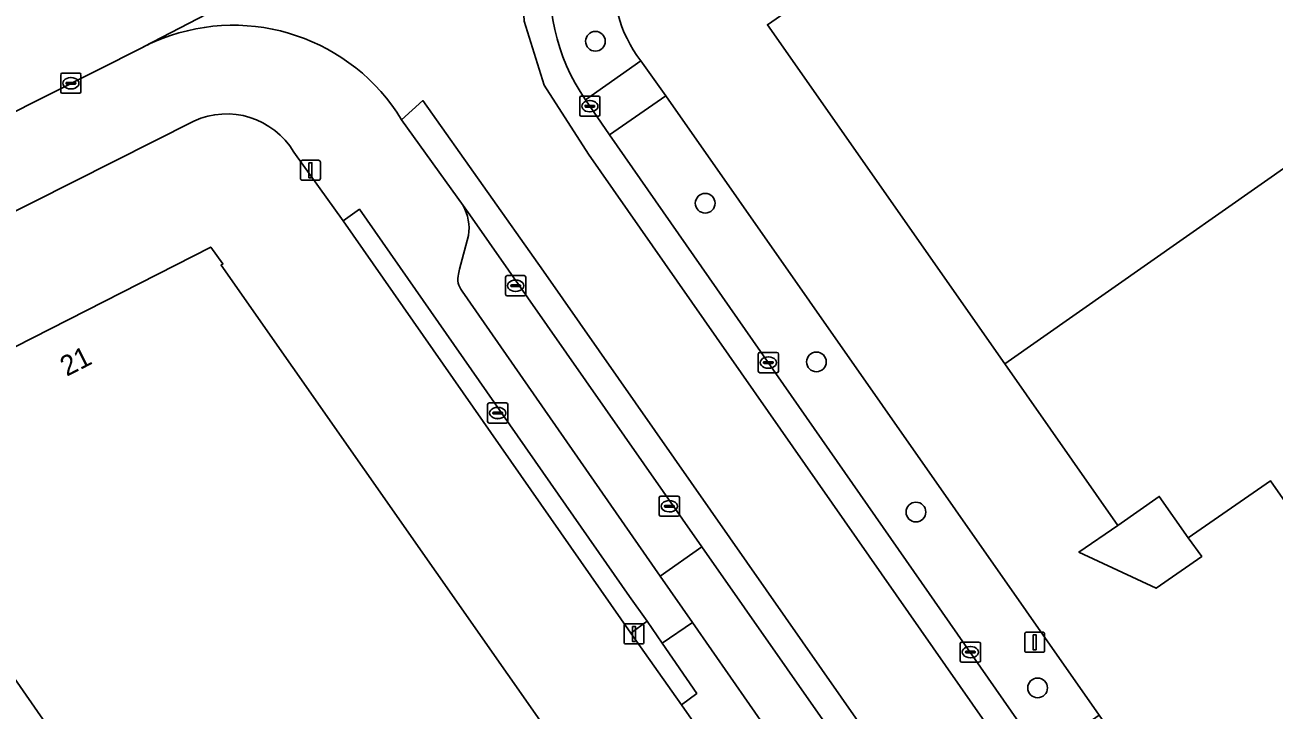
# Model space of a CAD drawing. Extents: x 156702 to 158052, y 387630 to 388992.
# Drawn here: x 157140.6 to 157202.6, y 388268.5 to 388302.5 of the extents above; entities that cross this region are included whole.
import ezdxf

# ---------------------------------------------------------------- set-up
doc = ezdxf.new("R2010")
doc.units = 0
for name, color, linetype in [('IMGEO_Berm_groen', 7, 'Continuous'), ('IMGEO_Boom', 7, 'Continuous'), ('IMGEO_Brandkraan', 7, 'Continuous'), ('IMGEO_Erf', 7, 'Continuous'), ('IMGEO_Groenvoorziening', 7, 'Continuous'), ('IMGEO_Kolk', 7, 'Continuous'), ('IMGEO_Lichtmast', 7, 'Continuous'), ('IMGEO_Pand', 7, 'Continuous'), ('IMGEO_Pand_nummerreeks', 7, 'Continuous'), ('IMGEO_Pand_overbouw', 7, 'Continuous'), ('IMGEO_Parkeervlak_open', 7, 'Continuous'), ('IMGEO_Rijbaan_lokaal_gesloten', 7, 'Continuous'), ('IMGEO_Rijbaan_lokaal_open', 7, 'Continuous'), ('IMGEO_Verkeersbordpaal', 7, 'Continuous'), ('IMGEO_Voetpad_open', 7, 'Continuous')]:
    doc.layers.add(name, color=color, linetype=linetype)

msp = doc.modelspace()

# ---------------------------------------------------------------- linework, layer by layer
at = {"layer": 'IMGEO_Berm_groen'}
msp.add_lwpolyline([(157168.386, 388298.814), (157171.132, 388300.752)], dxfattribs=at)
msp.add_lwpolyline([(157172.367, 388299.009), (157169.573, 388297.067), (157191.042, 388266.266), (157192.324, 388267.155), (157193.882, 388268.245)], close=True, dxfattribs=at)
for centre, radius, start, end in [((157176.376, 388304.395), 9.746, 124.73394, 214.93326), ((157176.005, 388304.567), 6.189, 122.60722, 218.05882)]:
    msp.add_arc(centre, radius, start, end, dxfattribs=at)
at = {"layer": 'IMGEO_Boom'}
for centre in [(157168.877, 388301.714), (157174.325, 388293.674), (157179.849, 388285.794), (157184.788, 388278.337), (157190.826, 388269.605)]:
    msp.add_circle(centre, 0.489, dxfattribs=at)
at = {"layer": 'IMGEO_Brandkraan'}
for p, q in [((157163.602, 388283.754), (157164.454, 388283.754)), ((157163.527, 388282.828), (157163.527, 388283.68)), ((157163.786, 388283.248), (157163.786, 388283.26)), ((157164.224, 388283.211), (157163.826, 388283.211)), ((157163.829, 388283.297), (157164.227, 388283.297)), ((157164.015, 388283.534), (157164.04, 388283.534)), ((157164.27, 388283.26), (157164.27, 388283.248)), ((157164.528, 388283.68), (157164.528, 388282.828)), ((157164.454, 388282.754), (157163.602, 388282.754)), ((157164.038, 388282.974), (157164.013, 388282.974))]:
    msp.add_line(p, q, dxfattribs=at)
for points in [[(157163.602, 388283.754), (157164.454, 388283.754)], [(157163.527, 388282.828), (157163.527, 388283.68)], [(157164.528, 388283.68), (157164.528, 388282.828)], [(157164.454, 388282.754), (157163.602, 388282.754)]]:
    msp.add_lwpolyline(points, dxfattribs=at)
for centre, radius, start, end in [((157163.604, 388283.678), 0.0765, 91.55205, 178.44795), ((157163.604, 388283.678), 0.0765, 91.55205, 178.44795), ((157164.452, 388283.678), 0.0765, 1.55205, 88.44795), ((157164.452, 388283.678), 0.0765, 1.55205, 88.44795), ((157163.826, 388283.257), 0.0403, 85.87752, 175.75265), ((157163.823, 388283.247), 0.0366, 178.93798, 274.71019), ((157164.227, 388283.254), 0.043, 264.86636, 352.45326), ((157164.231, 388283.259), 0.0386, 1.73085, 96.63898), ((157163.604, 388282.83), 0.0765, 181.55205, 268.44795), ((157163.604, 388282.83), 0.0765, 181.55205, 268.44795), ((157164.452, 388282.83), 0.0765, 271.55205, 358.44795), ((157164.452, 388282.83), 0.0765, 271.55205, 358.44795)]:
    msp.add_arc(centre, radius, start, end, dxfattribs=at)
for centre, major_axis, ratio, start_param, end_param in [((157164.014, 388283.254), (-0.387, 0.002), 0.722429, 4.712389, 7.853982), ((157164.039, 388283.254), (-0.39, 0.002), 0.717154, 1.570796, 4.712389)]:
    msp.add_ellipse(centre, major_axis=major_axis, ratio=ratio, start_param=start_param, end_param=end_param, dxfattribs=at)
at = {"layer": 'IMGEO_Erf'}
for points in [[(157219.61, 388264.167), (157215.353, 388270.292), (157211.106, 388267.393), (157202.392, 388279.88), (157198.304, 388277.05), (157196.864, 388279.117), (157194.804, 388277.677), (157189.199, 388285.691), (157177.415, 388302.539), (157179.467, 388303.97), (157178.197, 388305.797), (157187.143, 388310.419), (157188.937, 388307.859), (157198.347, 388314.459), (157201.175, 388310.421), (157208.838, 388299.477), (157224.658, 388276.883), (157252.506, 388296.33)], [(157171.132, 388300.752), (157172.367, 388299.009), (157193.882, 388268.245), (157194.975, 388266.682), (157200.032, 388259.496), (157200.786, 388258.42), (157207.925, 388248.229), (157212.342, 388241.924), (157218.512, 388233.115), (157232.439, 388213.235), (157238.976, 388203.904), (157243.285, 388197.598), (157250.344, 388187.533), (157253.951, 388182.374), (157260.401, 388173.229), (157265.086, 388166.567), (157269.88, 388159.622), (157271.116, 388157.832), (157273.661, 388154.215), (157277.716, 388148.352), (157281.526, 388142.848), (157289.3, 388131.616), (157294.457, 388124.387)], [(157148.941, 388297.754), (157138.985, 388292.726), (157128.27, 388287.322), (157128.049, 388287.211), (157126.181, 388286.269), (157116.605, 388281.44), (157113.566, 388279.867), (157099.732, 388272.877), (157085.63, 388265.739), (157083.745, 388264.78), (157064.77, 388255.035), (157056.22, 388250.104), (157054.047, 388248.702), (157044.401, 388242.479)], [(157242.574, 388169.007), (157241.87, 388169.99), (157236.847, 388177.226), (157236.169, 388178.201), (157228.416, 388189.316), (157222.314, 388197.962), (157192.467, 388240.777), (157190.75, 388243.22), (157186.236, 388249.801), (157179.863, 388258.901), (157178.825, 388260.626), (157177.984, 388261.818), (157175.156, 388265.898), (157173.142, 388268.766), (157170.643, 388272.326), (157156.349, 388292.803), (157153.912, 388296.208)], [(157131.214, 388282.046), (157149.786, 388291.491), (157150.383, 388290.659), (157150.298, 388290.598), (157168.087, 388265.189), (157151.414, 388253.673), (157156.538, 388246.255), (157134.3, 388234.974)]]:
    msp.add_lwpolyline(points, dxfattribs=at)
for centre, radius, start, end in [((157176.005, 388304.567), 6.189, 122.60722, 218.05882), ((157150.567, 388294.216), 3.893, 30.76678, 114.68143)]:
    msp.add_arc(centre, radius, start, end, dxfattribs=at)
at = {"layer": 'IMGEO_Groenvoorziening'}
for points in [[(157170.576, 388274.137), (157157.166, 388293.377), (157156.349, 388292.803), (157170.643, 388272.326), (157171.438, 388272.911)], [(157172.19, 388271.819), (157171.438, 388272.911), (157170.643, 388272.326), (157173.142, 388268.766), (157173.906, 388269.329)]]:
    msp.add_lwpolyline(points, close=True, dxfattribs=at)
at = {"layer": 'IMGEO_Kolk'}
for p, q in [((157142.339, 388299.205), (157142.339, 388300.057)), ((157142.414, 388300.131), (157143.266, 388300.131)), ((157142.827, 388299.911), (157142.852, 388299.911)), ((157143.34, 388300.057), (157143.34, 388299.205)), ((157142.598, 388299.625), (157142.598, 388299.637)), ((157143.036, 388299.588), (157142.638, 388299.588)), ((157142.641, 388299.674), (157143.039, 388299.674)), ((157142.85, 388299.351), (157142.825, 388299.351)), ((157143.082, 388299.637), (157143.082, 388299.625)), ((157143.266, 388299.131), (157142.414, 388299.131)), ((157168.1, 388298.065), (157168.1, 388298.917)), ((157168.175, 388298.991), (157169.027, 388298.991)), ((157168.588, 388298.771), (157168.613, 388298.771)), ((157169.101, 388298.917), (157169.101, 388298.065)), ((157168.359, 388298.485), (157168.359, 388298.497)), ((157168.797, 388298.448), (157168.399, 388298.448)), ((157168.402, 388298.534), (157168.8, 388298.534)), ((157168.611, 388298.211), (157168.586, 388298.211)), ((157168.843, 388298.497), (157168.843, 388298.485)), ((157169.027, 388297.991), (157168.175, 388297.991)), ((157164.417, 388289.15), (157164.417, 388290.002)), ((157164.492, 388290.076), (157165.344, 388290.076)), ((157165.418, 388290.002), (157165.418, 388289.15)), ((157164.676, 388289.57), (157164.676, 388289.582)), ((157165.114, 388289.533), (157164.716, 388289.533)), ((157164.719, 388289.619), (157165.117, 388289.619)), ((157164.905, 388289.856), (157164.93, 388289.856)), ((157165.16, 388289.582), (157165.16, 388289.57)), ((157165.344, 388289.076), (157164.492, 388289.076)), ((157164.928, 388289.296), (157164.903, 388289.296)), ((157177.038, 388286.258), (157177.89, 388286.258)), ((157176.963, 388285.332), (157176.963, 388286.184)), ((157177.222, 388285.752), (157177.222, 388285.764)), ((157177.66, 388285.715), (157177.262, 388285.715)), ((157177.265, 388285.801), (157177.663, 388285.801)), ((157177.451, 388286.038), (157177.476, 388286.038)), ((157177.706, 388285.764), (157177.706, 388285.752)), ((157177.964, 388286.184), (157177.964, 388285.332)), ((157177.89, 388285.258), (157177.038, 388285.258)), ((157177.474, 388285.478), (157177.449, 388285.478)), ((157172.044, 388278.2), (157172.044, 388279.052)), ((157172.119, 388279.126), (157172.971, 388279.126)), ((157172.532, 388278.906), (157172.557, 388278.906)), ((157173.045, 388279.052), (157173.045, 388278.2)), ((157172.303, 388278.62), (157172.303, 388278.632)), ((157172.741, 388278.583), (157172.343, 388278.583)), ((157172.346, 388278.669), (157172.744, 388278.669)), ((157172.555, 388278.346), (157172.53, 388278.346)), ((157172.787, 388278.632), (157172.787, 388278.62)), ((157172.971, 388278.126), (157172.119, 388278.126)), ((157186.989, 388270.955), (157186.989, 388271.807)), ((157187.064, 388271.881), (157187.916, 388271.881)), ((157187.248, 388271.375), (157187.248, 388271.387)), ((157187.291, 388271.424), (157187.689, 388271.424)), ((157187.477, 388271.661), (157187.502, 388271.661)), ((157187.732, 388271.387), (157187.732, 388271.375)), ((157187.99, 388271.807), (157187.99, 388270.955)), ((157187.916, 388270.881), (157187.064, 388270.881)), ((157187.686, 388271.338), (157187.288, 388271.338)), ((157187.5, 388271.101), (157187.475, 388271.101))]:
    msp.add_line(p, q, dxfattribs=at)
for points in [[(157142.339, 388299.205), (157142.339, 388300.057)], [(157142.414, 388300.131), (157143.266, 388300.131)], [(157143.34, 388300.057), (157143.34, 388299.205)], [(157143.266, 388299.131), (157142.414, 388299.131)], [(157168.1, 388298.065), (157168.1, 388298.917)], [(157168.175, 388298.991), (157169.027, 388298.991)], [(157169.101, 388298.917), (157169.101, 388298.065)], [(157169.027, 388297.991), (157168.175, 388297.991)], [(157164.417, 388289.15), (157164.417, 388290.002)], [(157164.492, 388290.076), (157165.344, 388290.076)], [(157165.418, 388290.002), (157165.418, 388289.15)], [(157165.344, 388289.076), (157164.492, 388289.076)], [(157177.038, 388286.258), (157177.89, 388286.258)], [(157176.963, 388285.332), (157176.963, 388286.184)], [(157177.964, 388286.184), (157177.964, 388285.332)], [(157177.89, 388285.258), (157177.038, 388285.258)], [(157172.044, 388278.2), (157172.044, 388279.052)], [(157172.119, 388279.126), (157172.971, 388279.126)], [(157173.045, 388279.052), (157173.045, 388278.2)], [(157172.971, 388278.126), (157172.119, 388278.126)], [(157186.989, 388270.955), (157186.989, 388271.807)], [(157187.064, 388271.881), (157187.916, 388271.881)], [(157187.99, 388271.807), (157187.99, 388270.955)], [(157187.916, 388270.881), (157187.064, 388270.881)]]:
    msp.add_lwpolyline(points, dxfattribs=at)
for centre, radius, start, end in [((157142.416, 388300.055), 0.0765, 91.55205, 178.44795), ((157142.416, 388300.055), 0.0765, 91.55205, 178.44795), ((157143.264, 388300.055), 0.0765, 1.55205, 88.44795), ((157143.264, 388300.055), 0.0765, 1.55205, 88.44795), ((157142.638, 388299.634), 0.0403, 85.87752, 175.75265), ((157142.635, 388299.624), 0.0366, 178.93798, 274.71019), ((157143.039, 388299.631), 0.043, 264.86636, 352.45326), ((157143.043, 388299.636), 0.0386, 1.73085, 96.63898), ((157142.416, 388299.207), 0.0765, 181.55205, 268.44795), ((157142.416, 388299.207), 0.0765, 181.55205, 268.44795), ((157143.264, 388299.207), 0.0765, 271.55205, 358.44795), ((157143.264, 388299.207), 0.0765, 271.55205, 358.44795), ((157168.177, 388298.915), 0.0765, 91.55205, 178.44795), ((157168.177, 388298.915), 0.0765, 91.55205, 178.44795), ((157169.025, 388298.915), 0.0765, 1.55205, 88.44795), ((157169.025, 388298.915), 0.0765, 1.55205, 88.44795), ((157168.177, 388298.067), 0.0765, 181.55205, 268.44795), ((157168.177, 388298.067), 0.0765, 181.55205, 268.44795), ((157168.399, 388298.494), 0.0403, 85.87752, 175.75265), ((157168.396, 388298.484), 0.0366, 178.93798, 274.71019), ((157168.8, 388298.491), 0.043, 264.86636, 352.45326), ((157168.804, 388298.496), 0.0386, 1.73085, 96.63898), ((157169.025, 388298.067), 0.0765, 271.55205, 358.44795), ((157169.025, 388298.067), 0.0765, 271.55205, 358.44795), ((157164.494, 388290), 0.0765, 91.55205, 178.44795), ((157164.494, 388290), 0.0765, 91.55205, 178.44795), ((157165.342, 388290), 0.0765, 1.55205, 88.44795), ((157165.342, 388290), 0.0765, 1.55205, 88.44795), ((157164.716, 388289.579), 0.0403, 85.87752, 175.75265), ((157164.713, 388289.569), 0.0366, 178.93798, 274.71019), ((157165.117, 388289.576), 0.043, 264.86636, 352.45326), ((157165.121, 388289.581), 0.0386, 1.73085, 96.63898), ((157164.494, 388289.152), 0.0765, 181.55205, 268.44795), ((157164.494, 388289.152), 0.0765, 181.55205, 268.44795), ((157165.342, 388289.152), 0.0765, 271.55205, 358.44795), ((157165.342, 388289.152), 0.0765, 271.55205, 358.44795), ((157177.04, 388286.182), 0.0765, 91.55205, 178.44795), ((157177.04, 388286.182), 0.0765, 91.55205, 178.44795), ((157177.888, 388286.182), 0.0765, 1.55205, 88.44795), ((157177.888, 388286.182), 0.0765, 1.55205, 88.44795), ((157177.262, 388285.761), 0.0403, 85.87752, 175.75265), ((157177.259, 388285.751), 0.0366, 178.93798, 274.71019), ((157177.663, 388285.758), 0.043, 264.86636, 352.45326), ((157177.667, 388285.763), 0.0386, 1.73085, 96.63898), ((157177.04, 388285.334), 0.0765, 181.55205, 268.44795), ((157177.04, 388285.334), 0.0765, 181.55205, 268.44795), ((157177.888, 388285.334), 0.0765, 271.55205, 358.44795), ((157177.888, 388285.334), 0.0765, 271.55205, 358.44795), ((157172.121, 388279.05), 0.0765, 91.55205, 178.44795), ((157172.121, 388279.05), 0.0765, 91.55205, 178.44795), ((157172.969, 388279.05), 0.0765, 1.55205, 88.44795), ((157172.969, 388279.05), 0.0765, 1.55205, 88.44795), ((157172.121, 388278.202), 0.0765, 181.55205, 268.44795), ((157172.121, 388278.202), 0.0765, 181.55205, 268.44795), ((157172.343, 388278.629), 0.0403, 85.87752, 175.75265), ((157172.34, 388278.619), 0.0366, 178.93798, 274.71019), ((157172.744, 388278.626), 0.043, 264.86636, 352.45326), ((157172.748, 388278.631), 0.0386, 1.73085, 96.63898), ((157172.969, 388278.202), 0.0765, 271.55205, 358.44795), ((157172.969, 388278.202), 0.0765, 271.55205, 358.44795), ((157187.066, 388271.805), 0.0765, 91.55205, 178.44795), ((157187.066, 388271.805), 0.0765, 91.55205, 178.44795), ((157187.288, 388271.384), 0.0403, 85.87752, 175.75265), ((157187.285, 388271.374), 0.0366, 178.93798, 274.71019), ((157187.689, 388271.381), 0.043, 264.86636, 352.45326), ((157187.693, 388271.386), 0.0386, 1.73085, 96.63898), ((157187.914, 388271.805), 0.0765, 1.55205, 88.44795), ((157187.914, 388271.805), 0.0765, 1.55205, 88.44795), ((157187.066, 388270.957), 0.0765, 181.55205, 268.44795), ((157187.066, 388270.957), 0.0765, 181.55205, 268.44795), ((157187.914, 388270.957), 0.0765, 271.55205, 358.44795), ((157187.914, 388270.957), 0.0765, 271.55205, 358.44795)]:
    msp.add_arc(centre, radius, start, end, dxfattribs=at)
for centre, major_axis, ratio, start_param, end_param in [((157142.826, 388299.631), (-0.387, 0.002), 0.722429, 4.712389, 7.853982), ((157142.851, 388299.631), (-0.39, 0.002), 0.717154, 1.570796, 4.712389), ((157168.587, 388298.491), (-0.387, 0.002), 0.722429, 4.712389, 7.853982), ((157168.612, 388298.491), (-0.39, 0.002), 0.717154, 1.570796, 4.712389), ((157164.904, 388289.576), (-0.387, 0.002), 0.722429, 4.712389, 7.853982), ((157164.929, 388289.576), (-0.39, 0.002), 0.717154, 1.570796, 4.712389), ((157177.45, 388285.758), (-0.387, 0.002), 0.722429, 4.712389, 7.853982), ((157177.475, 388285.758), (-0.39, 0.002), 0.717154, 1.570796, 4.712389), ((157172.531, 388278.626), (-0.387, 0.002), 0.722429, 4.712389, 7.853982), ((157172.556, 388278.626), (-0.39, 0.002), 0.717154, 1.570796, 4.712389), ((157187.476, 388271.381), (-0.387, 0.002), 0.722429, 4.712389, 7.853982), ((157187.501, 388271.381), (-0.39, 0.002), 0.717154, 1.570796, 4.712389)]:
    msp.add_ellipse(centre, major_axis=major_axis, ratio=ratio, start_param=start_param, end_param=end_param, dxfattribs=at)
at = {"layer": 'IMGEO_Lichtmast'}
for p, q in [((157154.236, 388294.91), (157154.236, 388295.71)), ((157154.236, 388295.71), (157154.236, 388294.91)), ((157154.336, 388295.81), (157155.126, 388295.81)), ((157155.126, 388295.81), (157154.336, 388295.81)), ((157155.226, 388295.71), (157155.226, 388294.91)), ((157155.226, 388294.91), (157155.226, 388295.71)), ((157155.126, 388294.81), (157154.336, 388294.81)), ((157154.336, 388294.81), (157155.126, 388294.81)), ((157170.296, 388271.886), (157170.296, 388272.686)), ((157170.296, 388272.686), (157170.296, 388271.886)), ((157170.396, 388272.786), (157171.186, 388272.786)), ((157171.186, 388272.786), (157170.396, 388272.786)), ((157171.286, 388272.686), (157171.286, 388271.886)), ((157171.286, 388271.886), (157171.286, 388272.686)), ((157171.186, 388271.786), (157170.396, 388271.786)), ((157170.396, 388271.786), (157171.186, 388271.786))]:
    msp.add_line(p, q, dxfattribs=at)
for points in [[(157154.656, 388295.685), (157154.806, 388295.685), (157154.806, 388294.935), (157154.656, 388294.935), (157154.656, 388295.685)], [(157170.716, 388272.661), (157170.866, 388272.661), (157170.866, 388271.911), (157170.716, 388271.911), (157170.716, 388272.661)]]:
    msp.add_lwpolyline(points, dxfattribs=at)
for centre, start, end in [((157154.336, 388295.71), 90, 180), ((157154.336, 388295.71), 90, 180), ((157155.126, 388295.71), 0, 90), ((157155.126, 388295.71), 360, 90), ((157154.336, 388294.91), 180, 270), ((157154.336, 388294.91), 180, 270), ((157155.126, 388294.91), 270, 0), ((157155.126, 388294.91), 270, 0), ((157170.396, 388272.686), 90, 180), ((157170.396, 388272.686), 90, 180), ((157171.186, 388272.686), 0, 90), ((157171.186, 388272.686), 360, 90), ((157170.396, 388271.886), 180, 270), ((157170.396, 388271.886), 180, 270), ((157171.186, 388271.886), 270, 0), ((157171.186, 388271.886), 270, 0)]:
    msp.add_arc(centre, 0.1, start, end, dxfattribs=at)
at = {"layer": 'IMGEO_Pand'}
for points in [[(157189.199, 388285.691), (157208.838, 388299.477), (157201.175, 388310.421), (157198.347, 388314.459), (157188.937, 388307.859), (157187.143, 388310.419), (157178.197, 388305.797), (157179.467, 388303.97), (157177.415, 388302.539)], [(157224.658, 388276.883), (157208.838, 388299.477), (157189.199, 388285.691), (157194.804, 388277.677), (157196.864, 388279.117), (157198.304, 388277.05), (157202.392, 388279.88), (157211.106, 388267.393), (157215.353, 388270.292)], [(157150.298, 388290.598), (157150.383, 388290.659), (157149.786, 388291.491), (157131.214, 388282.046), (157132.082, 388280.851), (157132.433, 388281.028), (157148.354, 388258.104), (157151.414, 388253.673), (157168.087, 388265.189)], [(157132.433, 388281.028), (157132.082, 388280.851), (157128.809, 388279.204), (157128.117, 388280.546), (157120.809, 388276.868), (157116.316, 388274.608), (157119.653, 388268.139), (157119.249, 388267.935), (157113.32, 388264.949), (157134.3, 388234.974), (157156.538, 388246.255), (157151.414, 388253.673), (157148.354, 388258.104)]]:
    msp.add_lwpolyline(points, close=True, dxfattribs=at)
at = {"layer": 'IMGEO_Pand_overbouw'}
msp.add_lwpolyline([(157194.804, 388277.677), (157192.876, 388276.35), (157196.709, 388274.55), (157198.972, 388276.136), (157198.304, 388277.05), (157196.864, 388279.117)], close=True, dxfattribs=at)
at = {"layer": 'IMGEO_Parkeervlak_open'}
for points in [[(157162.255, 388289.305), (157172.086, 388275.161), (157174.157, 388276.608), (157162.638, 388293.099)], [(157162.638, 388293.099), (157162.309, 388293.557)], [(157162.578, 388292.073), (157162.138, 388290.399), (157162.077, 388290.154)]]:
    msp.add_lwpolyline(points, dxfattribs=at)
for centre, radius, start, end in [((157160.258, 388292.419), 2.346, 351.52533, 29.0232), ((157163.049, 388289.915), 1.001, 166.17042, 217.51165)]:
    msp.add_arc(centre, radius, start, end, dxfattribs=at)
at = {"layer": 'IMGEO_Rijbaan_lokaal_gesloten'}
for points in [[(157064.311, 388259.963), (157069.269, 388262.524), (157081.717, 388268.807), (157083.645, 388269.772), (157096.097, 388276.064), (157113.037, 388284.606), (157114.576, 388285.374), (157124.187, 388290.222), (157124.485, 388290.372), (157126.055, 388291.164), (157126.271, 388291.273), (157136.976, 388296.673), (157146.433, 388301.427), (157146.447, 388301.446), (157171.244, 388314.319), (157180.605, 388319.095), (157279.127, 388368.703)], [(157290.068, 388122.059), (157284.128, 388130.537), (157250.785, 388178.4), (157218.017, 388225.194), (157168.536, 388296.106), (157166.328, 388299.54), (157165.346, 388302.72), (157165.232, 388304.849), (157165.572, 388307.171), (157166.44, 388309.461), (157166.862, 388310.136), (157167.285, 388310.812), (157167.449, 388311.074), (157168.134, 388311.902), (157169.086, 388312.83), (157170.115, 388313.613), (157170.159, 388313.64), (157171.244, 388314.319), (157146.447, 388301.446), (157146.433, 388301.427)], [(157170.823, 388312.404), (157166.862, 388310.136), (157166.44, 388309.461), (157165.572, 388307.171), (157165.232, 388304.849), (157165.346, 388302.72), (157166.328, 388299.54), (157168.536, 388296.106), (157218.017, 388225.194), (157250.785, 388178.4), (157284.128, 388130.537), (157290.068, 388122.059)], [(157159.256, 388297.816), (157160.307, 388298.772), (157166.301, 388290.299), (157236.347, 388190.018), (157288.771, 388114.767), (157287.657, 388113.917), (157306.474, 388095.88), (157307.404, 388097.063), (157338.534, 388071.878), (157341.899, 388076.038), (157340.456, 388076.982), (157309.901, 388101.717)], [(157293.74, 388119.458), (157291.999, 388121.743), (157285.376, 388131.195), (157279.247, 388139.992), (157275.903, 388144.791), (157269.683, 388153.769), (157268.767, 388155.125), (157267.467, 388156.891), (157263.265, 388162.929), (157256.455, 388172.746), (157252.169, 388178.864), (157246.429, 388187.061), (157241.532, 388194.055), (157234.617, 388203.884), (157230.6, 388209.644), (157214.539, 388232.609), (157210.521, 388238.352), (157203.933, 388247.771), (157199.027, 388254.836), (157191.042, 388266.266), (157169.573, 388297.067), (157168.386, 388298.814)]]:
    msp.add_lwpolyline(points, dxfattribs=at)
msp.add_lwpolyline([(157166.301, 388290.299), (157160.307, 388298.772), (157159.256, 388297.816), (157162.309, 388293.557), (157162.638, 388293.099), (157174.157, 388276.608), (157180.506, 388267.519), (157183.303, 388263.514), (157191.992, 388251.074), (157225.926, 388202.493), (157233.871, 388191.118), (157236.036, 388188.018), (157274.579, 388132.691), (157280.876, 388123.651), (157287.657, 388113.917), (157288.771, 388114.767), (157236.347, 388190.018)], close=True, dxfattribs=at)
for centre, radius, start, end in [((157176.376, 388304.395), 9.746, 124.73394, 214.93326), ((157150.905, 388292.736), 9.775, 31.31286, 111.21974), ((157150.787, 388293.015), 9.472, 111.16336, 117.36353)]:
    msp.add_arc(centre, radius, start, end, dxfattribs=at)
at = {"layer": 'IMGEO_Rijbaan_lokaal_open'}
msp.add_lwpolyline([(157174.157, 388276.608), (157172.086, 388275.161), (157173.692, 388272.854), (157178.419, 388266.061), (157180.506, 388267.519)], close=True, dxfattribs=at)
at = {"layer": 'IMGEO_Verkeersbordpaal'}
for p, q in [((157190.185, 388271.472), (157190.185, 388272.272)), ((157190.185, 388272.272), (157190.185, 388271.472)), ((157190.285, 388272.372), (157191.075, 388272.372)), ((157191.075, 388272.372), (157190.285, 388272.372)), ((157191.175, 388272.272), (157191.175, 388271.472)), ((157191.175, 388271.472), (157191.175, 388272.272)), ((157191.075, 388271.372), (157190.285, 388271.372)), ((157190.285, 388271.372), (157191.075, 388271.372))]:
    msp.add_line(p, q, dxfattribs=at)
msp.add_lwpolyline([(157190.605, 388272.247), (157190.755, 388272.247), (157190.755, 388271.497), (157190.605, 388271.497), (157190.605, 388272.247)], dxfattribs=at)
for centre, start, end in [((157190.285, 388272.272), 90, 180), ((157190.285, 388272.272), 90, 180), ((157191.075, 388272.272), 0, 90), ((157191.075, 388272.272), 360, 90), ((157190.285, 388271.472), 180, 270), ((157190.285, 388271.472), 180, 270), ((157191.075, 388271.472), 270, 0), ((157191.075, 388271.472), 270, 0)]:
    msp.add_arc(centre, 0.1, start, end, dxfattribs=at)
at = {"layer": 'IMGEO_Voetpad_open'}
for points in [[(157146.433, 388301.427), (157136.976, 388296.673), (157138.985, 388292.726), (157148.941, 388297.754)], [(157162.309, 388293.557), (157159.256, 388297.816)], [(157153.912, 388296.208), (157156.349, 388292.803), (157157.166, 388293.377), (157170.576, 388274.137), (157171.438, 388272.911), (157172.19, 388271.819), (157173.692, 388272.854), (157172.086, 388275.161), (157162.255, 388289.305)], [(157162.077, 388290.154), (157162.138, 388290.399), (157162.578, 388292.073)]]:
    msp.add_lwpolyline(points, dxfattribs=at)
for points in [[(157169.573, 388297.067), (157172.367, 388299.009), (157171.132, 388300.752), (157168.386, 388298.814)], [(157173.692, 388272.854), (157172.19, 388271.819), (157173.906, 388269.329), (157173.142, 388268.766), (157175.156, 388265.898), (157177.984, 388261.818), (157178.785, 388262.366), (157178.723, 388262.455), (157180.227, 388263.465), (157178.419, 388266.061)]]:
    msp.add_lwpolyline(points, close=True, dxfattribs=at)
for centre, radius, start, end in [((157150.905, 388292.736), 9.775, 31.31286, 111.21974), ((157150.787, 388293.015), 9.472, 111.16336, 117.36353), ((157150.567, 388294.216), 3.893, 30.76678, 114.68143), ((157160.258, 388292.419), 2.346, 351.52533, 29.0232), ((157163.049, 388289.915), 1.001, 166.17042, 217.51165)]:
    msp.add_arc(centre, radius, start, end, dxfattribs=at)

# ---------------------------------------------------------------- texts
at = {"layer": 'IMGEO_Pand_nummerreeks'}
msp.add_text('21', height=1, rotation=26.95766, dxfattribs=at).set_placement((157142.633, 388285.049))

doc.saveas('drawing.dxf')
